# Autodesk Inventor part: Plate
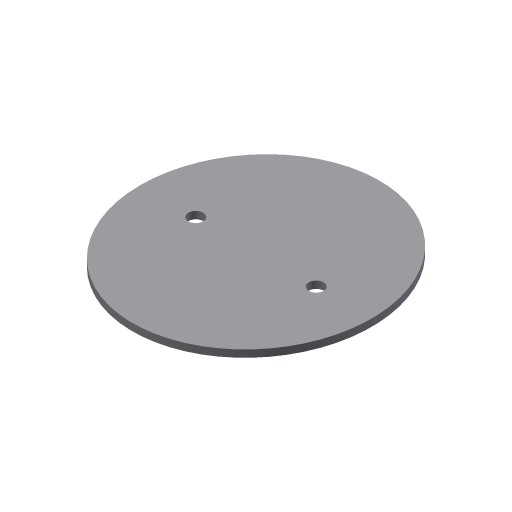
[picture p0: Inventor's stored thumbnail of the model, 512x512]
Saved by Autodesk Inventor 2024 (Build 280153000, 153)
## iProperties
Created: 2009-04
Part Number: Plate
Document SubType Name: Modeling
Designer: Sham
Density: 1 g/cm^3
Material: Generic
Appearance: Default
Author: Sham
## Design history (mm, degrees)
sketch "Sketch1"
  geometry: C1 r 6.25 at (-50, 0); C2 r 6.25 at (50, 0); 4 further points
  constraints: 2 centre point, 1 coincident, 5 other
  dimensions: "d1" = 12.5 diameter of C1; "d2" = 12.5 diameter of C2; "d3" = 100 distance of C2.centre C1.centre; "d4" = 102.5 distance of point (0, 0) point (0, 102.5); "d5" = 96 distance of point (0, 0) point (-96, 0); "d6" = 50 distance of point (0, 0) C1.centre
extrude "Extrusion1" new body sketch "Sketch1" distance "d7" = 6; taper "d8" = 0 deg
body "Solid1"
